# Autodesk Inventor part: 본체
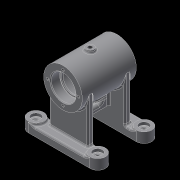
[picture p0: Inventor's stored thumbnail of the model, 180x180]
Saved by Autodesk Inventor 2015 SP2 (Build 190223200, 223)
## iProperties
Created: 2015-11
Part Number: 본체
Material: 일반
Document SubType Name: Modeling
Designer: AMC
Density: 1 g/cm^3
Appearance: 기본값
Author: AMC
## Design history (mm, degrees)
sketch "스케치2"
  geometry: L1 (-40, 30)-(40, 30); L2 (-40, 20)-(40, 20); L3 (40, 40)-(-40, 40); A1 r 10 centre (-40, 30) between (-40, 40) and (-40, 20); A2 r 10 centre (40, 30) between (40, 20) and (40, 40); 2 further points
  constraints: 8 end point, 4 point on circle, 4 tangent, 2 centre point, 1 horizontal, 1 midpoint, 1 parallel, 1 vertical alignment
  dimensions: "d8" = 20 distance between parallel lines of L2 L3; "d11" = 80 distance of L3.start L3.end; "d13" = 40 distance from line of point (0, 0) L3
extrude "돌출1" new body sketch "스케치2" distance "d14" = 10; taper "d15" = 0 deg
sketch "스케치3"
  geometry: C1 r 10 at (40, 30); C2 r 10 at (-40, 30); A1 r 10 centre (-40, 30) between (-40, 40) and (-40, 20) reference; A2 r 10 centre (40, 30) between (40, 20) and (40, 40) reference; 1 further point
  constraints: 4 concentric, 2 centre point
extrude "돌출2" join sketch "스케치3" distance "d16" = 3; taper "d17" = 0 deg
hole "구멍1" diameter "d20" = 12; stored, may be unused: countersink angle "d24" = 90 deg, drill point angle "d26" = 0 deg; dims "d18" = 10, "d19" = 10, "d21" = 6, "d22" = 4, "d23" = 2, "d25" = 4
hole "구멍2" diameter "d29" = 6; stored, may be unused: countersink angle "d33" = 90 deg, drill point angle "d35" = 0 deg; dims "d27" = 10, "d28" = 10, "d30" = 6, "d31" = 4, "d32" = 2, "d34" = 4
chamfer "모따기1" distance "d36" = 1; stored, may be unused: second distance "d37" = 2, angle "d38" = 45 deg
fillet "모깎기1" dims "d39" = 0.3
fillet "모깎기3" dims "d41" = 2
fillet "모깎기4" dims "d42" = 2
sketch "스케치4"
  geometry: L1 (-25, 20)-(25, 20); L2 (25, 20)-(25, 28); L3 (25, 28)-(-25, 28); L4 (-25, 28)-(-25, 20); L5 (-33.367, 20)-(33.367, 20) reference; 2 further points
  constraints: 8 end point, 2 parallel, 1 collinear, 1 horizontal, 1 midpoint, 1 perpendicular, 1 vertical alignment
  dimensions: "d43" = 50 distance of L1.start L1.end; "d44" = 8 distance between parallel lines of L3 L1
extrude "돌출3" join sketch "스케치4" distance "d45" = 58; taper "d46" = 0 deg
sketch "스케치7"
  geometry: L1 (-40, 0)-(40, 0) reference; C1 r 25 at (0, 68); 1 further point
  constraints: 1 centre point
  dimensions: "d58" = 68 distance from line of L1 C1.centre; "d59" = 50 diameter of C1
extrude "돌출6" join sketch "스케치7" stored distance "d60" = 70; taper "d61" = 0 deg
node "작업 평면3"
sketch "스케치8"
  geometry: C1 r 5 at (0, 0); 1 further point
  constraints: 1 centre point, 1 coincident
  dimensions: "d63" = 10 diameter of C1
extrude "돌출7" join sketch "스케치8" stored distance "d64" = 70; taper "d65" = 0 deg; stored distance "d120" = 28
node "작업 평면4"
  node "작업축2"
sketch "스케치9"
  geometry: L1 (-56.011, 0)-(56.011, 0) reference; C1 r 6 at (0, 0); 1 further point
  constraints: 1 centre point, 1 midpoint, 1 vertical alignment
  dimensions: "d67" = 12 diameter of C1
extrude "돌출8" join sketch "스케치9" distance "d68" = 28; taper "d69" = 0 deg
sketch "스케치10"
  geometry: L1 (-17.206, 23)-(20, 23); L2 (-35, 43)-(35, 43) reference; L3 (20, 10)-(20, 68) reference; 1 further point
  constraints: 2 end point, 1 horizontal, 1 point on line
  dimensions: "d70" = 20 distance between parallel lines of L1 L2
feature "리브1" sketch "스케치10" dims "d71" = 1, "d72" = 8, "d73" = 0, "d74" = 0, "d75" = 1, "d76" = 1
sketch "스케치11"
  geometry: L1 (-35, 84)-(-23, 84); L2 (-23, 84)-(-23, 82); L3 (-23, 82)-(-21, 82); L4 (-21, 82)-(-21, 89); L5 (-21, 89)-(21, 89); L6 (21, 89)-(21, 82); L7 (21, 82)-(23, 82); L8 (23, 82)-(23, 84); L9 (23, 84)-(35, 84); L10 (35, 84)-(35, 68); L11 (35, 68)-(-35, 68); L12 (-35, 68)-(-35, 84); L13 (-35, 93)-(-35, 43) reference; L14 (35, 43)-(35, 93) reference; 1 further point
  constraints: 24 end point, 8 perpendicular, 4 point on line, 2 collinear, 1 horizontal, 1 vertical
  dimensions: "d77" = 32 diameter of L9 L11; "d78" = 42 diameter of L5 L11; "d79" = 2 distance between parallel lines of L8 L6; "d80" = 2 distance between parallel lines of L4 L2; "d81" = 12 distance between parallel lines of L10 L8; "d82" = 12 distance between parallel lines of L2 L12; "d83" = 28 diameter of L7 L11; "d84" = 136 diameter of point (0, 0) L11
revolve "회전1" sketch "스케치11" stored, may be unused: angle "d85" = 90 deg
fillet "모깎기7" dims "d86" = 0.3
fillet "모깎기8" dims "d87" = 3
hole "구멍3" diameter "d90" = 5.188; stored, may be unused: countersink angle "d94" = 90 deg, drill point angle "d96" = 0 deg; dims "d88" = 10, "d89" = 10, "d91" = 12, "d92" = 4, "d93" = 2, "d95" = 16
hole "구멍4" diameter "d99" = 5.188; stored, may be unused: countersink angle "d103" = 90 deg, drill point angle "d105" = 0 deg; dims "d97" = 10, "d98" = 10, "d100" = 12, "d101" = 4, "d102" = 2, "d104" = 16
sketch "스케치12" dims "d106" = 40
  geometry: C1 r 25 at (0, 0) reference; 3 further points
  constraints: 2 horizontal alignment, 3 other
hole "구멍5" sketch "스케치12" at (20, 0) diameter "d107" = 3.242; stored, may be unused: countersink angle "d111" = 90 deg, drill point angle "d113" = 118 deg; dims "d108" = 8, "d109" = 4, "d110" = 2, "d112" = 10
sketch "스케치13"
  geometry: L1 (10.322, 12)-(10.322, 28); L2 (13.822, 12)-(13.822, 28); L3 (6.822, 28)-(6.822, 12); L4 (43.322, 60)-(43.322, 40) reference; A1 r 3.5 centre (10.322, 12) between (6.822, 12) and (13.822, 12); A2 r 3.5 centre (10.322, 28) between (13.822, 28) and (6.822, 28); 2 further points
  constraints: 8 end point, 4 point on circle, 4 tangent, 2 centre point, 1 horizontal alignment, 1 midpoint, 1 parallel, 1 vertical
  dimensions: "d117" = 33 distance between parallel lines of L4 L1; "d118" = 3.5 radius of A2; "d119" = 23 dimension on A2 A1
extrude "돌출9" cut sketch "스케치13" stored distance "d120" = 28; taper "d121" = 0 deg
fillet "모깎기10" dims "d123" = 2
fillet "모깎기11" dims "d124" = 2
fillet "모깎기12" dims "d125" = 2
fillet "모깎기13" dims "d126" = 2
fillet "모깎기14" dims "d127" = 2
node "작업 평면5"
sketch "스케치14"
  geometry: L1 (-25, 5)-(25, 5); L2 (25, 5)-(25, -5); L3 (25, -5)-(-25, -5); L4 (-25, -5)-(-25, 5); L5 (25, 0)-(-25, 0); L6 (0, -5)-(0, 5); L7 (35, 25)-(-35, 25) reference; L8 (-35, 25)-(-35, -25) reference; 1 further point
  constraints: 4 end point, 4 midpoint, 2 other
  dimensions: "d128" = 50 distance of L1.start L1.end; "d129" = 10 distance between parallel lines of L1 L3; "d130" = 25 distance between parallel lines of L7 L5; "d131" = 35 distance between parallel lines of L8 L6
feature "엠보싱1" sketch "스케치14" dims "d23" = 2, "d132" = 0.5, "d133" = 0
chamfer "모따기2" distance "d134" = 1; stored, may be unused: second distance "d135" = 2, angle "d136" = 45 deg
fillet "모깎기15" dims "d137" = 3.5
node "솔리드1"
mirror "대칭1"
mirror "대칭2"
pattern_circular "원형 패턴1" dims angle "d115" = 360 deg
mirror "대칭3"
other parameters: "d62" = 96, "d66" = 60 deg
